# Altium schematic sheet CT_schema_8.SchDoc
size 274 x 160 mm
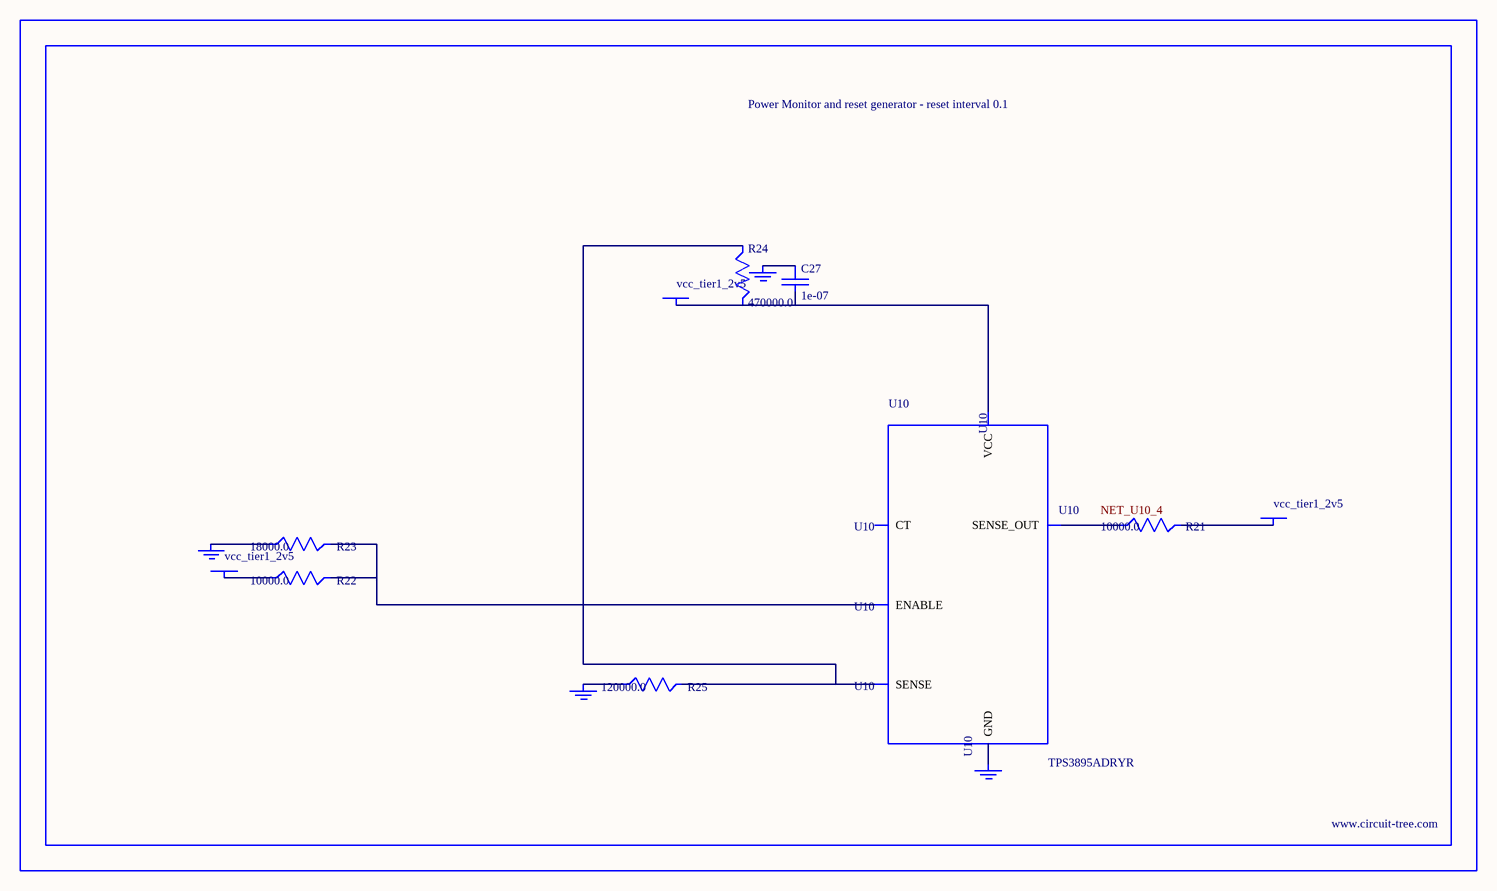
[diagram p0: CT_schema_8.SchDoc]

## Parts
BORDER7  (no value)
C27  1e-07  [C0402]
GND_INSTANCE_7_0  (no value)
GND_INSTANCE_7_1  (no value)
GND_INSTANCE_7_2  (no value)
GND_INSTANCE_7_3  (no value)
POWER_INSTANCE_7_0  vcc_tier1_2v5
POWER_INSTANCE_7_1  vcc_tier1_2v5
POWER_INSTANCE_7_2  vcc_tier1_2v5
R21  10000.0  [R0603]
R22  10000.0  [R0603]
R23  18000.0  [R0603]
R24  470000.0  [R0603]
R25  120000.0  [R0603]
U10  TPS3895ADRYR  [SON-6]

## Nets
NetC27_1: C27.1 GND_INSTANCE_7_2.0(GND)
NetC27_2: C27.2 POWER_INSTANCE_7_2.0(PWR) R24.2 U10.6(VCC)
NetGND_INSTANCE_7_0_0: GND_INSTANCE_7_0.0(GND) R23.1
NetGND_INSTANCE_7_1_0: GND_INSTANCE_7_1.0(GND) R25.1
NetGND_INSTANCE_7_3_0: GND_INSTANCE_7_3.0(GND) U10.2(GND)
NetPOWER_INSTANCE_7_0_0: POWER_INSTANCE_7_0.0(PWR) R22.1
NetPOWER_INSTANCE_7_1_0: POWER_INSTANCE_7_1.0(PWR) R21.2
NetR21_1: R21.1 U10.4(SENSE_OUT)
NetR22_2: R22.2 R23.2 U10.1(ENABLE)
NetR24_1: R24.1 R25.2 U10.3(SENSE)

Not connected (* = marked no-connect by the designer): U10 5(CT)

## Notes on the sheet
- Labels drawn without touching a wire or pin: NET_U10_4

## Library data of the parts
BORDER7 = BORDER_PAGE7
C27 = C0402C104K3RACTU
GND_INSTANCE_7_0-GND_INSTANCE_7_3 = GND
POWER_INSTANCE_7_0-POWER_INSTANCE_7_2 = PWR
R21 R22 = RC0603JR-0710KL
R23 = RC0603JR-0718KL
R24 = RC0603JR-07470KL
R25 = RC0603JR-07120KL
